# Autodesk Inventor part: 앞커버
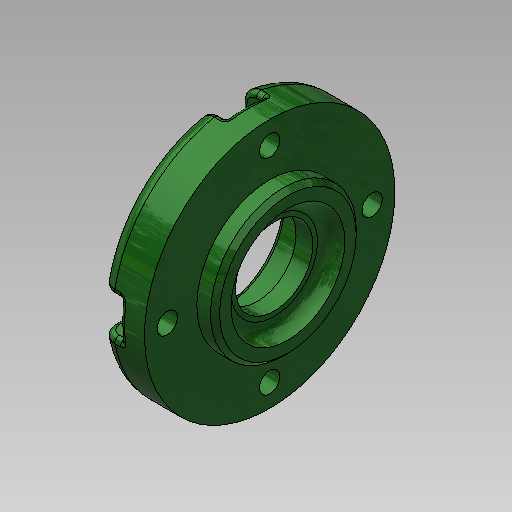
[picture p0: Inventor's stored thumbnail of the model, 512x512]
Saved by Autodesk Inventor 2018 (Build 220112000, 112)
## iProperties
Created: 2015-11
Part Number: 앞커버
Material: 알루미늄 6061
Document SubType Name: Modeling
Designer: mduedu
Density: 1 g/cm^3
Appearance: 매끄러움 - 짙은 산림 녹색
Author: mduedu
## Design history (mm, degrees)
sketch "스케치1"
  geometry: L1 (-7, 0)-(7, 0); L2 (-7, 0)-(-7, 27.5); L3 (-7, 27.5)-(3, 27.5); L4 (3, 27.5)-(3, 16); L5 (3, 16)-(7, 16); L6 (7, 16)-(7, 0); 2 further points
  constraints: 12 end point, 3 perpendicular, 2 parallel, 1 coincident, 1 horizontal, 1 midpoint
  dimensions: "d0" = 14 distance of L1.start L1.end; "d1" = 55 diameter of L3 L1; "d2" = 4 distance of L4.end L5.end; "d3" = 32 diameter of L5 L1
revolve "회전1" sketch "스케치1" stored, may be unused: angle "d4" = 90 deg
hole "구멍1" diameter "d7" = 25; stored, may be unused: countersink angle "d11" = 90 deg, drill point angle "d13" = 0 deg; dims "d5" = 10, "d6" = 10, "d8" = 6, "d9" = 4, "d10" = 2, "d12" = 3
hole "구멍2" diameter "d16" = 25; stored, may be unused: countersink angle "d20" = 90 deg, drill point angle "d22" = 0 deg; dims "d17" = 6, "d18" = 4, "d19" = 2, "d21" = 7.3, "d61" = 10, "d62" = 10
hole "구멍3" diameter "d25" = 17; stored, may be unused: countersink angle "d29" = 90 deg, drill point angle "d31" = 0 deg; dims "d23" = 10, "d24" = 10, "d26" = 6, "d27" = 4, "d28" = 2, "d30" = 4.2
chamfer "모따기1" distance "d32" = 0.7; stored, may be unused: second distance "d33" = 2, angle "d34" = 30 deg
fillet "모깎기1" dims "d35" = 0.3
fillet "모깎기2" dims "d36" = 3
fillet "모깎기3" dims "d37" = 3
sketch "스케치2" dims "d39" = 45
  geometry: C1 r 12.904 at (0, 0) reference; C2 r 24.5 at (0, 0) reference; 6 further points
  constraints: 2 vertical alignment, 1 coincident, 7 other
  dimensions: "d42" = 360 deg dimension on point (0, 0) point (0, 22.5) (derived)
sketch "스케치3"
  geometry: 8 further points
  constraints: 4 coincident
hole "구멍4" sketch "스케치3" at (-22.5, 0), (0, -22.5), (22.5, 0), (0, 22.5) diameter "d44" = 4.5; stored, may be unused: countersink angle "d48" = 90 deg, drill point angle "d50" = 0 deg; dims "d45" = 6, "d46" = 8, "d47" = 4.6, "d49" = 8
sketch "스케치4"
  geometry: L1 (-4, 0)-(-4, -4.708); L2 (4, 0)-(4, -4.708); A1 r 4 centre (0, 0) between (-4, 0) and (4, 0) reference; A2 r 27.5 centre (0, 22.5) between (-4, -4.708) and (4, -4.708) reference; 3 further points
  constraints: 4 end point, 4 point on circle, 2 tangent, 1 parallel, 1 vertical
extrude "돌출1" cut sketch "스케치4" extent not by distance; stored distance "d51" = 0; taper "d52" = 0 deg
fillet "모깎기5" dims "d56" = 0.3
fillet "모깎기6" dims "d57" = 1
chamfer "모따기2" distance "d63" = 1; stored, may be unused: second distance "d64" = 2, angle "d65" = 45 deg
node "솔리드1"
pattern_circular "원형 패턴1" dims angle "d54" = 360 deg
